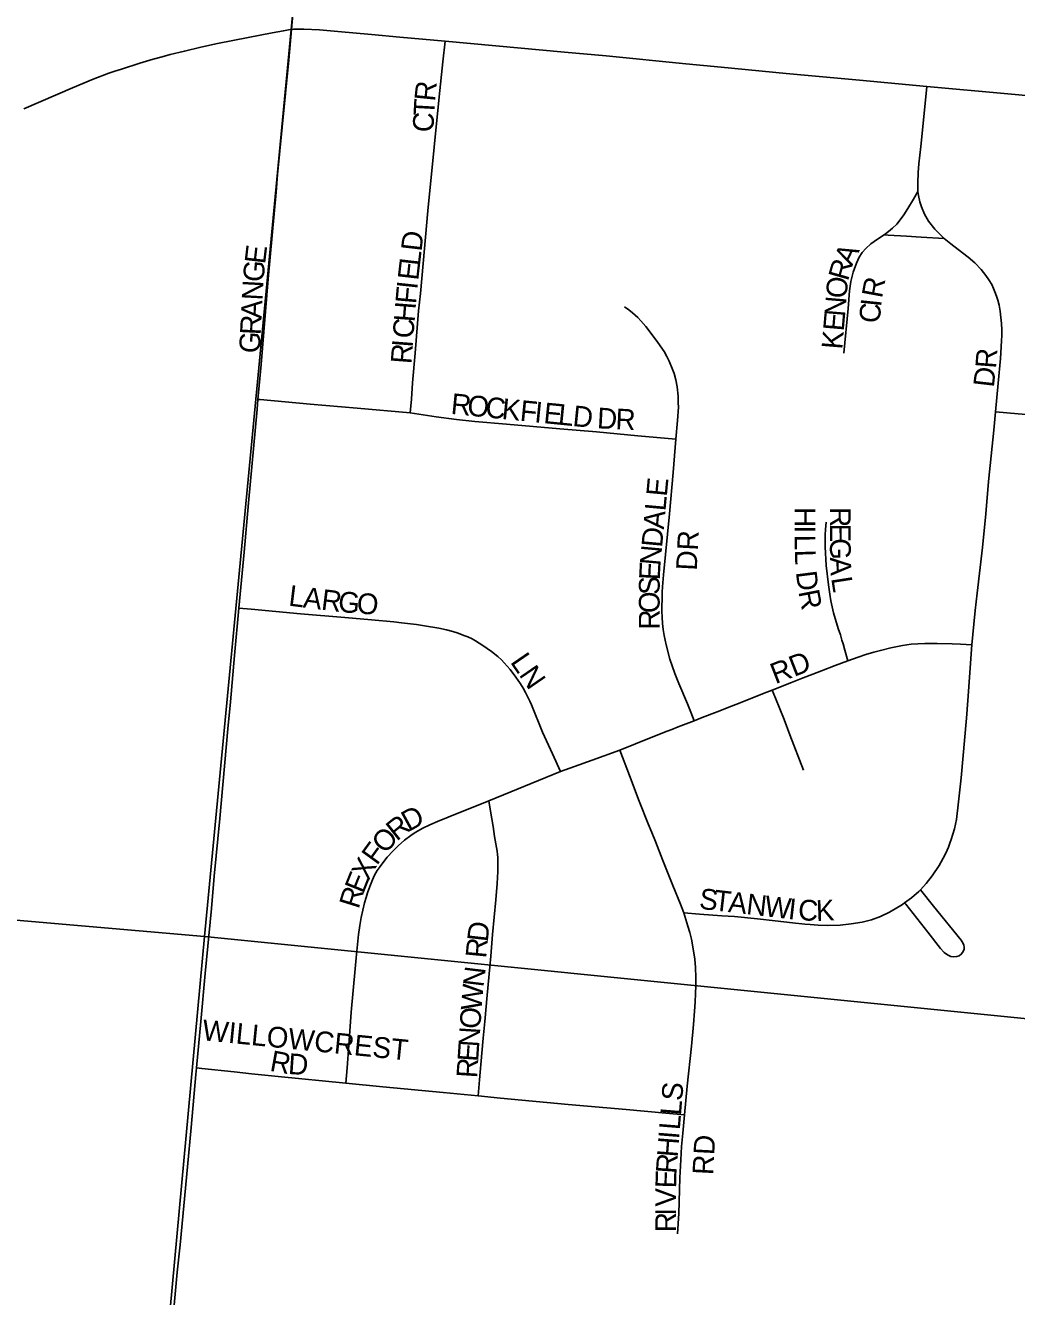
# Model space of a CAD drawing. Extents: x 1410790 to 1770854, y 448063 to 770588.
# Drawn here: x 1522235 to 1524624, y 629663 to 632726 of the extents above; entities that cross this region are included whole.
import ezdxf

# ---------------------------------------------------------------- set-up
doc = ezdxf.new("R2010")
doc.units = 0
for name, color, linetype in [('GM_X_City_Street', 7, 'Continuous'), ('GM_X_City_Street_Text', 7, 'Continuous'), ('GM_X_Section', 7, 'Continuous')]:
    doc.layers.add(name, color=color, linetype=linetype)

msp = doc.modelspace()

# ---------------------------------------------------------------- linework, layer by layer
at = {"layer": 'GM_X_City_Street'}
for points in [[(1522876.5, 632715.6), (1522885.6, 632816.8), (1522900.1, 632970.4), (1522903.5, 633004.3)], [(1522231.5, 632524.2), (1522349.1, 632574.9), (1522398.6, 632595.8), (1522436.3, 632610.1), (1522450.7, 632615.3), (1522466.7, 632620.5), (1522511.4, 632634.4), (1522543.5, 632643.9), (1522565.2, 632650), (1522583.9, 632655.2), (1522618.6, 632663.9), (1522658.1, 632673), (1522698.5, 632681.7), (1522772.3, 632696.5), (1522830, 632707.8), (1522856.9, 632712.9), (1522869.4, 632714.7), (1522876.5, 632715.6)], [(1522795.6, 631824.6), (1522803.3, 631908.8), (1522820.2, 632114.7), (1522839.2, 632323.8), (1522843.1, 632366.4), (1522854.4, 632480.1), (1522870.1, 632642.4), (1522876.5, 632715.6)], [(1522876.5, 632715.6), (1522881.7, 632716.2), (1522892.4, 632716.6), (1522906.1, 632716.6), (1522943.7, 632714.7), (1522988.4, 632711.2), (1523069.6, 632703.6), (1523137.3, 632697.6), (1523246.5, 632687.5)], [(1523162.7, 631791.7), (1523165.6, 631825.2), (1523168.2, 631864.4), (1523174.4, 631936.2), (1523183, 632037.5), (1523187.5, 632079.9), (1523193.6, 632151.8), (1523205.2, 632279.1), (1523220.3, 632432.5), (1523232.8, 632553.2), (1523241.5, 632638.1), (1523246.5, 632687.5)], [(1523246.5, 632687.5), (1523369.1, 632676.3), (1523534.8, 632661.1), (1523634.7, 632652), (1523826.5, 632633.3), (1523912, 632625.1), (1524068.7, 632609.9), (1524157.3, 632601.6), (1524245.4, 632593.4), (1524407.4, 632578.3)], [(1524385.7, 632325.6), (1524386.2, 632346.6), (1524387.2, 632370.8), (1524388.8, 632391.8), (1524392.9, 632433.6), (1524403, 632529), (1524407.4, 632578.3)], [(1524407.4, 632578.3), (1524602.6, 632560.5), (1524725.4, 632549.2), (1524880.8, 632534.5), (1524972, 632525.8), (1524991, 632524)], [(1524304.8, 632221), (1524315.1, 632229.1), (1524325, 632236.8), (1524335.3, 632246.9), (1524341.3, 632253.8), (1524352.5, 632269.4), (1524362.2, 632284.6), (1524375.9, 632306.8), (1524385.7, 632325.6)], [(1524449.7, 632212), (1524442.8, 632218.2), (1524427.2, 632234.3), (1524411.5, 632254.1), (1524402.4, 632270.9), (1524394.7, 632288.4), (1524390.8, 632300.4), (1524387.5, 632315.7), (1524385.7, 632325.6)], [(1524208, 631935.5), (1524217.9, 632043.8), (1524221.5, 632086.2), (1524224.8, 632108.8), (1524230.2, 632131), (1524237.8, 632152.5), (1524244.9, 632167.2), (1524252, 632178.2), (1524260.4, 632188.1), (1524272.5, 632199.2), (1524288.5, 632210.6), (1524304.8, 632221)], [(1524304.8, 632221), (1524314.4, 632220.5), (1524359, 632217.7), (1524394.2, 632215.5), (1524449.7, 632212)], [(1524573.2, 631794.5), (1524579.7, 631863.9), (1524584.9, 631922.9), (1524588, 631965.3), (1524588.2, 631978.2), (1524588.3, 631991.9), (1524587.5, 632007.4), (1524586.3, 632021.8), (1524584.6, 632036.8), (1524582.1, 632051.4), (1524578.7, 632063.7), (1524575.8, 632072.8), (1524571.7, 632083.6), (1524568.6, 632091.3), (1524564.2, 632100.9), (1524557.2, 632112.8), (1524549.7, 632123.1), (1524538.6, 632137.6), (1524523.7, 632153.1), (1524507.4, 632167.3), (1524483.6, 632185.6), (1524465.5, 632199.3), (1524449.7, 632211.9), (1524449.7, 632212)], [(1523802.9, 631728.4), (1523807.1, 631773.2), (1523808.9, 631805.9), (1523808.8, 631816.1), (1523808.1, 631832.1), (1523805.7, 631854.7), (1523802.9, 631871.5), (1523798.8, 631886.5), (1523794.1, 631899.2), (1523786.7, 631916.7), (1523781.1, 631927.8), (1523774.3, 631939.5), (1523759.6, 631961.4), (1523743.1, 631983.6), (1523730.2, 632000.3), (1523718.4, 632013.8), (1523710.9, 632021.8), (1523704.8, 632027.7), (1523698.5, 632033), (1523689.2, 632040.2), (1523679.3, 632047.5)], [(1522749.6, 631321.5), (1522751.1, 631338.6), (1522762.4, 631456.2), (1522772.9, 631575.6), (1522793.5, 631801), (1522795.6, 631824.6)], [(1522795.6, 631824.6), (1522801, 631824.1), (1522921.3, 631813.2), (1523034.9, 631803.1), (1523162.7, 631791.7)], [(1523162.7, 631791.7), (1523225.3, 631782.5), (1523274.5, 631775.7), (1523318.7, 631770.8), (1523394.9, 631764.7), (1523523.5, 631753.7), (1523611.3, 631746.3), (1523711.6, 631736.7), (1523802.9, 631728.4)], [(1524515.9, 631233.1), (1524520.8, 631283), (1524524.4, 631315.4), (1524529.2, 631357.6), (1524541.8, 631467.7), (1524549.6, 631548.8), (1524556.5, 631627), (1524569.1, 631750.2), (1524573.2, 631794.5)], [(1524573.2, 631794.5), (1524627.4, 631789.8), (1524753.1, 631779), (1524867.1, 631769.1), (1524919.3, 631764.6)], [(1523847.2, 631050.2), (1523838.9, 631071.1), (1523831, 631091.1), (1523809.8, 631140.1), (1523800.1, 631164.2), (1523788.4, 631198.2), (1523779.1, 631233.1), (1523774.4, 631255.5), (1523772.1, 631270.2), (1523770.7, 631284.6), (1523769.6, 631299.5), (1523769.3, 631314), (1523769.1, 631329.2), (1523769.6, 631340.2), (1523770.2, 631359.7), (1523771, 631372.7), (1523771.6, 631382.4), (1523772.9, 631401.8), (1523777.5, 631451.1), (1523787.4, 631548.4), (1523796, 631648.3), (1523802.9, 631728.4)], [(1524217.3, 631194.4), (1524210.1, 631220), (1524205.8, 631235.3), (1524203.2, 631244.5), (1524199.5, 631256.9), (1524194.2, 631272.4), (1524182.6, 631309.9), (1524176.5, 631338.8), (1524174.1, 631354.9), (1524170.9, 631377.6), (1524165.4, 631424.4), (1524162.7, 631468.8), (1524162.8, 631498.4), (1524163.4, 631510.7), (1524164.8, 631528.6)], [(1522647.6, 630214), (1522657.8, 630325.2), (1522668.7, 630441.5), (1522683.4, 630598.1), (1522690.4, 630675.8), (1522703.6, 630814.6), (1522723.3, 631030.5), (1522729.3, 631095.5), (1522739.4, 631207.1), (1522749.6, 631321.5)], [(1522749.6, 631321.5), (1522779.1, 631318.8), (1522898, 631308), (1523005.4, 631298.6), (1523069.3, 631293.3), (1523123.4, 631288.2), (1523141.8, 631286.2), (1523178.1, 631281.7), (1523196.7, 631279.1), (1523231.6, 631273.1), (1523250.4, 631269.1), (1523265.5, 631265), (1523278.4, 631261), (1523292.2, 631255.9), (1523301.9, 631252.1), (1523311.7, 631247.3), (1523319.9, 631242.7), (1523338, 631231.7), (1523358.9, 631216.8), (1523373.5, 631205.3), (1523382.6, 631196.7), (1523389.4, 631190.1), (1523403.8, 631173.3), (1523417.4, 631155.3), (1523428.3, 631139.4), (1523434.8, 631128.3), (1523440.5, 631118.5), (1523445.7, 631108.6), (1523451.3, 631097.1), (1523455, 631088.3), (1523481.1, 631022.6), (1523505.2, 630970.2), (1523525, 630927.5)], [(1524217.3, 631194.4), (1524242.3, 631203.4), (1524260.9, 631209.6), (1524279.9, 631215.1), (1524295.7, 631219.5), (1524321.2, 631225.9), (1524348.8, 631231.3), (1524370, 631234.3), (1524386.3, 631235.4), (1524402.7, 631236.1), (1524432.3, 631236.4), (1524468.6, 631235.5), (1524488.5, 631234.5), (1524515.9, 631233.1)], [(1524392.2, 630643.1), (1524406.3, 630658.3), (1524420.7, 630676.5), (1524437.5, 630701.3), (1524447.3, 630718.7), (1524453.1, 630730.7), (1524459.6, 630745.8), (1524463.2, 630754.9), (1524466.5, 630764.1), (1524474.4, 630789.5), (1524479.1, 630812.5), (1524483.7, 630854.4), (1524490.7, 630912.7), (1524503.1, 631056.6), (1524506.3, 631098.9), (1524515.9, 631233.1)], [(1524035, 631124), (1524081.9, 631142.3), (1524106, 631151.8), (1524153.5, 631170.5), (1524187, 631183.4), (1524217.3, 631194.4)], [(1523847.2, 631050.2), (1523866.2, 631057.6), (1523902.3, 631071.8), (1523937.3, 631085.5), (1523958.2, 631093.7), (1524015.8, 631116.5), (1524035, 631124)], [(1524110.6, 630930.8), (1524077.8, 631016.3), (1524063.5, 631052.9), (1524042.8, 631104.5), (1524035, 631124)], [(1523667.7, 630979.6), (1523705.7, 630994.7), (1523739.1, 631008), (1523781.5, 631024.8), (1523793.5, 631029.4), (1523808.6, 631035.3), (1523847.2, 631050.2)], [(1523525, 630927.5), (1523558.3, 630939.7), (1523601.5, 630955.4), (1523667.7, 630979.6)], [(1523821.8, 630587.1), (1523814, 630608), (1523795.6, 630653.2), (1523781, 630689.5), (1523771.4, 630713.8), (1523753.4, 630759.3), (1523744.7, 630780.5), (1523736.5, 630801.8), (1523714.8, 630856), (1523690.8, 630918.2), (1523667.7, 630979.6)], [(1523351.9, 630857.4), (1523525, 630927.5)], [(1523007.8, 630176.9), (1523010.7, 630214.1), (1523014.7, 630268.2), (1523020.5, 630348), (1523030, 630452.6), (1523032.3, 630478.9), (1523035.3, 630511), (1523038.2, 630535), (1523041.2, 630556.7), (1523044.7, 630575.8), (1523048.4, 630593.7), (1523052.8, 630611.7), (1523056.2, 630624.1), (1523059.9, 630635.9), (1523065, 630650.9), (1523071.8, 630666.9), (1523076.7, 630677.8), (1523083.4, 630689.7), (1523090, 630699.3), (1523099.2, 630711.2), (1523107.3, 630721.1), (1523121.6, 630737), (1523133.8, 630748.6), (1523148.9, 630762.4), (1523164.3, 630773.8), (1523174.8, 630780.6), (1523192.8, 630791), (1523210.3, 630799.5), (1523228.1, 630807.6), (1523254.1, 630818.1), (1523351.9, 630857.4)], [(1523326.3, 630146.2), (1523329.7, 630184.8), (1523335.5, 630249.5), (1523338.4, 630285.3), (1523342.1, 630325.8), (1523347.8, 630389.1), (1523354.3, 630457.2), (1523356.8, 630483.3), (1523361.2, 630535.5), (1523369.3, 630618.8), (1523372.3, 630658.3), (1523373.6, 630686.7), (1523374.1, 630709.2), (1523373.5, 630720.6), (1523373.1, 630727.9), (1523372, 630736.2), (1523366.1, 630771.2), (1523362.2, 630795), (1523356.2, 630832.3), (1523351.9, 630857.4)], [(1524354.2, 630611.6), (1524370.6, 630623.1), (1524388.1, 630638.7), (1524392.2, 630643.1)], [(1524354.2, 630611.6), (1524357, 630608), (1524410, 630540.8), (1524440.4, 630501.7), (1524449.4, 630492), (1524457.2, 630485.9), (1524465.5, 630482.4), (1524473, 630481.1), (1524479.9, 630482), (1524486, 630484.1), (1524491.6, 630488.2), (1524495.5, 630493.9), (1524497.4, 630499.9), (1524497.5, 630504.8), (1524496.7, 630509.5), (1524495, 630513.5), (1524492.7, 630517.5), (1524490.2, 630521.1), (1524424, 630603.2), (1524392.2, 630643.1)], [(1523821.8, 630587.1), (1523859.7, 630584.3), (1523913.5, 630580.4), (1523944.5, 630578.1), (1523999.7, 630572.6), (1524042.1, 630568.1), (1524084.3, 630563.2), (1524113.5, 630560.2), (1524126.5, 630559), (1524146.1, 630557.6), (1524169.2, 630556.7), (1524199, 630557.8), (1524225.4, 630560.5), (1524251.7, 630564.7), (1524274.3, 630570.6), (1524296.4, 630578.7), (1524317.4, 630589), (1524348.7, 630607.7), (1524354.2, 630611.6)], [(1523823.8, 630100.6), (1523830.1, 630169.9), (1523840.4, 630266.4), (1523845.4, 630318.4), (1523848, 630350.6), (1523849.2, 630371.7), (1523850.4, 630393), (1523851.2, 630411.4), (1523850.8, 630431.7), (1523849.8, 630455.9), (1523848.2, 630475.4), (1523844.9, 630500.8), (1523840.4, 630524.2), (1523836.4, 630539.9), (1523832.1, 630555.3), (1523821.8, 630587.1)], [(1522421.4, 627845.6), (1522425.3, 627888), (1522437.4, 628018.6), (1522453.2, 628185.1), (1522464.7, 628306.1), (1522479.4, 628460.6), (1522492.5, 628600.8), (1522507.7, 628758.3), (1522518.5, 628867.2), (1522526.7, 628946.7), (1522537.6, 629053.5), (1522547.2, 629144.4), (1522555, 629222.7), (1522564.2, 629323.7), (1522575.7, 629450.7), (1522587.9, 629580.4), (1522601.4, 629721.4), (1522607.9, 629787.4), (1522626.1, 629975.3), (1522634.6, 630070.1), (1522646.1, 630197.5), (1522647.6, 630214)], [(1522647.6, 630214), (1522660.4, 630212.6), (1522738.2, 630203.9), (1522780.5, 630199.1), (1522844.4, 630192.8), (1523007.8, 630176.9)], [(1523007.8, 630176.9), (1523096.6, 630168.3), (1523242.2, 630154.3), (1523326.3, 630146.2)], [(1523326.3, 630146.2), (1523380.5, 630141.1), (1523543.1, 630125.5), (1523683.2, 630113.1), (1523778.9, 630104.6), (1523823.8, 630100.6)], [(1523806.4, 629813.9), (1523809.8, 629862.9), (1523812.7, 629948.8), (1523814.6, 629991.9), (1523816.8, 630024.6), (1523819.8, 630056.6), (1523823.8, 630100.6)]]:
    msp.add_lwpolyline(points, dxfattribs=at)
at = {"layer": 'GM_X_Section'}
for points in [[(1517870, 636321.1), (1523175.4, 635852.3), (1522667.1, 630530.5), (1517358.6, 630990.4)], [(1523175.4, 635852.3), (1528392.9, 635323.7), (1527942.6, 630003), (1522667.1, 630530.5)], [(1522667.1, 630530.5), (1522174.5, 625186.4), (1516936.9, 625665.1), (1516859.8, 625674.3), (1517358.6, 630990.4)], [(1527942.6, 630003), (1527484, 624666.3), (1522801.4, 625129.5), (1522174.5, 625186.4), (1522667.1, 630530.5)]]:
    msp.add_lwpolyline(points, close=True, dxfattribs=at)

# ---------------------------------------------------------------- texts
at = {"layer": 'GM_X_City_Street_Text'}
for s, rotation, p in [('R', 84.1855, (1523222.2, 632541.2)), ('T', 86.8156, (1523220.3, 632506.7)), ('C', 86.8175, (1523218.1, 632467.1)), ('D', 83.4824, (1523189.9, 632179.8)), ('E', 83.346, (1522812.9, 632149.1)), ('L', 83.4848, (1523185.9, 632144.9)), ('A', 64.5395, (1524227.4, 632143.9)), ('G', 84.483, (1522808.7, 632105.6)), ('E', 83.5256, (1523181.9, 632109.9)), ('R', 74.0729, (1524217.4, 632107.9)), ('O', 85.0875, (1524214, 632066.6)), ('R', 79.4758, (1524299.5, 632066.7)), ('N', 86.928, (1522806.4, 632062.2)), ('F', 84.9119, (1523176.5, 632053.3)), ('I', 83.8674, (1523179.6, 632088.1)), ('A', 87.1781, (1522804.2, 632018.3)), ('H', 85.5812, (1523173.1, 632009.6)), ('N', 85.1746, (1524210.3, 632022.7)), ('C', 84.7341, (1524293.8, 632006.6)), ('I', 84.0024, (1524297.4, 632045.9)), ('R', 87.1691, (1522802.2, 631978.8)), ('C', 85.5873, (1523170, 631970.1)), ('E', 85.1895, (1524207.4, 631987.7)), ('K', 85.1746, (1524203.7, 631943.8)), ('G', 87.1791, (1522800.1, 631934.8)), ('I', 85.5812, (1523168.3, 631948.1)), ('R', 85.5873, (1523165.3, 631908.7)), ('R', 85.6327, (1524574.2, 631897.8)), ('D', 83.3846, (1524569, 631852)), ('R', 354.3075, (1523259.2, 631789.7)), ('O', 354.2861, (1523298.6, 631785.8)), ('C', 354.2963, (1523342.4, 631781.4)), ('K', 354.2987, (1523381.8, 631777.5)), ('F', 354.3084, (1523425.6, 631773.1)), ('I', 354.2633, (1523460.6, 631769.6)), ('E', 354.3253, (1523482.6, 631767.4)), ('L', 354.3084, (1523517.6, 631763.9)), ('D', 354.3721, (1523552.7, 631760.4)), ('D', 356.9981, (1523612.1, 631754.9)), ('R', 357.5341, (1523656.6, 631752.5)), ('E', 84.7132, (1523781, 631589.2)), ('L', 84.7081, (1523777.7, 631554.1)), ('H', 270, (1524089, 631564.8)), ('R', 270.1457, (1524174.1, 631564.7)), ('A', 84.7027, (1523773.7, 631510.3)), ('D', 84.7135, (1523769.6, 631466.5)), ('DR', 86.9884, (1523853.1, 631411.2)), ('I', 270.077, (1524089, 631520.7)), ('E', 270.1503, (1524174.2, 631525.1)), ('N', 84.8352, (1523765.6, 631422.7)), ('L', 270.6167, (1524089, 631498.2)), ('G', 270.1421, (1524174.3, 631489.9)), ('L', 271.905, (1524089.4, 631461.8)), ('A', 272.5349, (1524174.4, 631443.7)), ('E', 87.0612, (1523763.9, 631388.1)), ('D', 277.2605, (1524091.9, 631408.4)), ('L', 352.9055, (1522867.9, 631327.7)), ('S', 89.7677, (1523763.8, 631353.5)), ('L', 278.8161, (1524177, 631393.7)), ('A', 352.9207, (1522902.8, 631323.3)), ('R', 352.9141, (1522946.5, 631317.9)), ('G', 354.6656, (1522987.4, 631312.9)), ('O', 356.3731, (1523032.8, 631308.6)), ('O', 89.942, (1523763.7, 631309.6)), ('R', 281.0344, (1524098, 631361.3)), ('R', 89.9393, (1523763.7, 631269.9)), ('LN', 304.5137, (1523402.4, 631191.7)), ('RD', 21.254, (1524042.7, 631138)), ('D', 28.6767, (1523159.1, 630782.1)), ('R', 38.5991, (1523130, 630758.7)), ('O', 48.0696, (1523102.2, 630727.5)), ('F', 53.9716, (1523082.3, 630700)), ('X', 61.0982, (1523062, 630662.9)), ('E', 68.021, (1523049.5, 630631.7)), ('R', 72.6634, (1523038, 630594.9)), ('S', 353.5104, (1523857.4, 630597.3)), ('T', 353.4833, (1523892.4, 630593.4)), ('A', 353.5139, (1523927.4, 630589.4)), ('N', 353.4945, (1523971.1, 630584.4)), ('W', 353.4964, (1524014.8, 630579.4)), ('I', 353.5185, (1524071.7, 630572.9)), ('C', 356.386, (1524096.3, 630570.2)), ('K', 2.1905, (1524141.3, 630567.6)), ('D', 83.7044, (1523349.4, 630515.9)), ('R', 84.5286, (1523345.6, 630476.7)), ('N', 82.9997, (1523339, 630406.9)), ('W', 85.2531, (1523334.3, 630350.4)), ('O', 86.2383, (1523331.5, 630306.7)), ('WILLOWCREST', 354.3434, (1522659.6, 630280.6)), ('N', 86.2492, (1523328.6, 630262.8)), ('R', 349.6713, (1522822.3, 630207)), ('D', 356.0828, (1522867.3, 630199.2)), ('E', 86.2463, (1523326.3, 630227.7)), ('R', 86.2449, (1523323.7, 630188.2)), ('S', 85.4179, (1523817.9, 630133.1)), ('L', 85.4303, (1523815.1, 630098.1)), ('L', 85.4179, (1523812.3, 630063)), ('H', 85.4269, (1523807, 629997.2)), ('I', 85.4287, (1523810.5, 630041)), ('RD', 86.989, (1523892.7, 629954.8)), ('R', 85.9767, (1523804.3, 629957.8)), ('E', 88.5105, (1523803.4, 629923.2)), ('V', 89.942, (1523803.3, 629879.5)), ('I', 89.9391, (1523803.3, 629857.5)), ('R', 89.9514, (1523803.3, 629817.9))]:
    msp.add_text(s, height=50, rotation=rotation, dxfattribs=at).set_placement(p)

doc.saveas('drawing.dxf')
